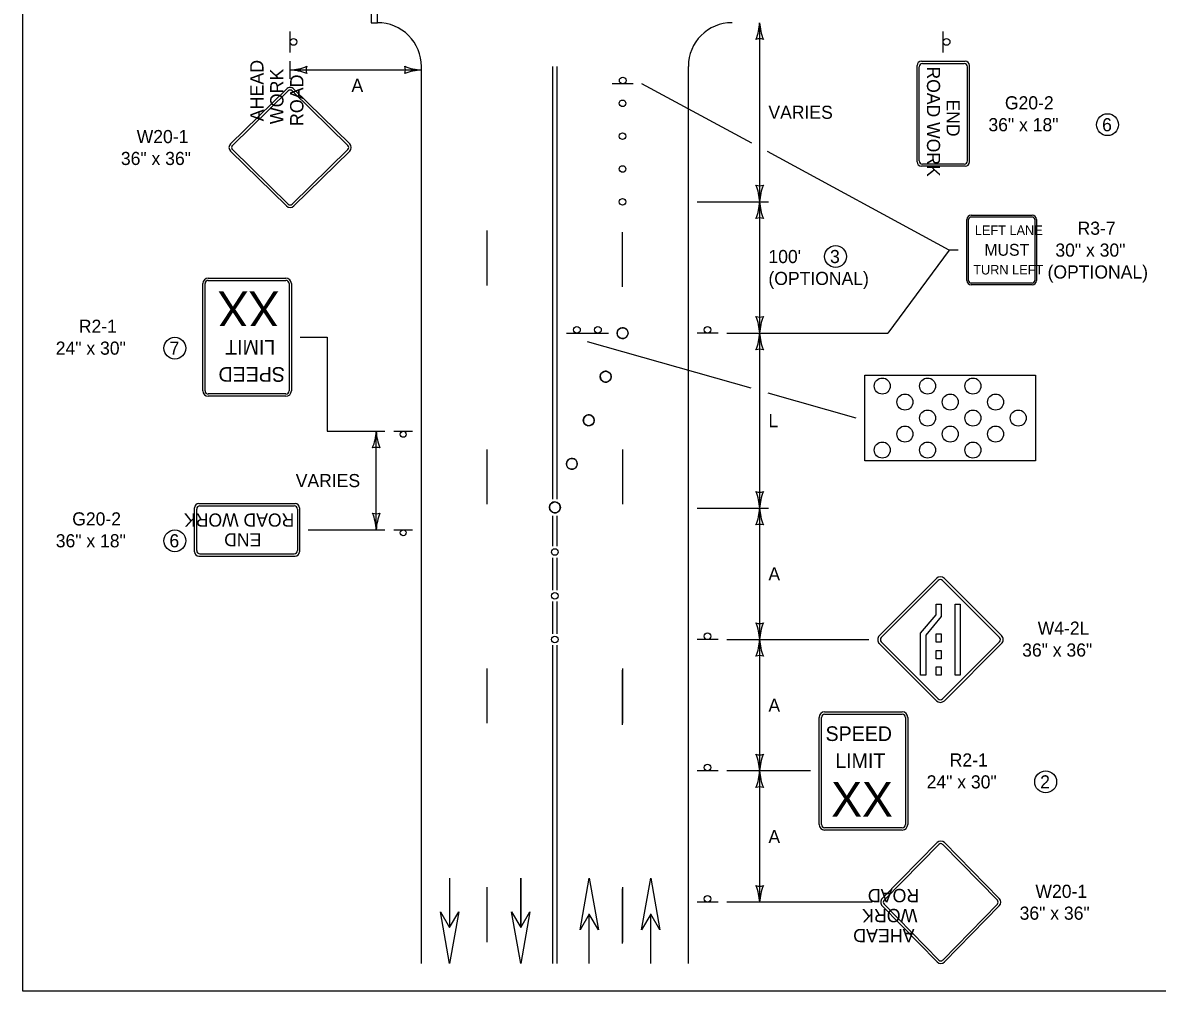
# Model space of a CAD drawing. Extents: x 49991.4 to 50021, y 49987.6 to 50011.4.
# Drawn here: x 49999.38 to 50004.57, y 49987.8 to 49992.22 of the extents above; entities that cross this region are included whole.
import ezdxf

# ---------------------------------------------------------------- set-up
doc = ezdxf.new("R2010")
doc.units = 0
for name, color, linetype in [('Level 1', 7, 'Continuous'), ('Level 2', 7, 'Continuous'), ('Level 3', 7, 'Continuous')]:
    doc.layers.add(name, color=color, linetype=linetype)

msp = doc.modelspace()

# ---------------------------------------------------------------- linework, layer by layer
at = {"layer": 'Level 1'}
for p, q in [((50000.6058, 49992.088), (50000.6058, 49992.184)), ((50003.5911, 49992.088), (50003.5911, 49992.184)), ((50001.2058, 49987.9261), (50001.2058, 49992.024)), ((50001.8058, 49990.0474), (50001.8058, 49992.024)), ((50001.8258, 49990.0474), (50001.8258, 49992.024)), ((50002.4258, 49987.9261), (50002.4258, 49992.024)), ((50003.471, 49991.5881), (50003.471, 49992.0281)), ((50003.4811, 49991.593), (50003.4811, 49992.023)), ((50003.4911, 49992.048), (50003.6911, 49992.048)), ((50003.4961, 49992.038), (50003.6861, 49992.038)), ((50003.7011, 49991.593), (50003.7011, 49992.023)), ((50003.7111, 49991.588), (50003.7111, 49992.028)), ((50000.3335, 49991.6709), (50000.5887, 49991.921)), ((50000.3417, 49991.6626), (50000.5969, 49991.9127)), ((50000.6147, 49991.9127), (50000.87, 49991.6626)), ((50000.6229, 49991.921), (50000.8782, 49991.6709)), ((50002.1738, 49991.945), (50002.0778, 49991.945)), ((50000.5969, 49991.395), (50000.3417, 49991.6451)), ((50000.87, 49991.6451), (50000.6147, 49991.395)), ((50000.5887, 49991.3866), (50000.3335, 49991.6367)), ((50000.8782, 49991.6367), (50000.6229, 49991.3866)), ((50003.6911, 49991.568), (50003.4911, 49991.568)), ((50003.6861, 49991.578), (50003.4961, 49991.578)), ((50003.7185, 49991.3443), (50003.9971, 49991.3443)), ((50003.7185, 49991.3364), (50003.9971, 49991.3364)), ((50003.6986, 49991.0458), (50003.6986, 49991.3244)), ((50003.7065, 49991.0458), (50003.7065, 49991.3244)), ((50004.0091, 49991.3244), (50004.0091, 49991.0458)), ((50004.017, 49991.3244), (50004.017, 49991.0458)), ((50001.5059, 49991.024), (50001.5059, 49991.274)), ((50002.1254, 49991.0167), (50002.1254, 49991.2667)), ((50000.2064, 49990.5424), (50000.2064, 49991.0319)), ((50000.2169, 49990.5424), (50000.2169, 49991.0319)), ((50000.2317, 49991.0572), (50000.5861, 49991.0572)), ((50000.2317, 49991.0466), (50000.5861, 49991.0466)), ((50000.6009, 49991.0319), (50000.6009, 49990.5424)), ((50000.6114, 49991.0319), (50000.6114, 49990.5424)), ((50003.6986, 49991.0458), (50003.6986, 49991.0458)), ((50003.7065, 49991.0458), (50003.7065, 49991.0458)), ((50003.9971, 49991.0338), (50003.7185, 49991.0338)), ((50003.9971, 49991.0259), (50003.7185, 49991.0259)), ((50002.1106, 49990.8258), (50002.1106, 49990.8258)), ((50001.8687, 49990.8057), (50001.9647, 49990.8057)), ((50001.9647, 49990.8057), (50002.0607, 49990.8057)), ((50002.5618, 49990.8057), (50002.4658, 49990.8057)), ((50002.0332, 49990.6268), (50002.0332, 49990.6268)), ((50000.5861, 49990.5277), (50000.2317, 49990.5277)), ((50000.5861, 49990.5171), (50000.2317, 49990.5171)), ((50000.4089, 49990.5171), (50000.4089, 49990.5171)), ((50001.9558, 49990.4277), (50001.9558, 49990.4277)), ((50001.0794, 49990.3571), (50001.1658, 49990.3571)), ((50001.5059, 49990.024), (50001.5059, 49990.274)), ((50002.1259, 49990.024), (50002.1259, 49990.274)), ((50001.8784, 49990.2287), (50001.8784, 49990.2287)), ((50000.1688, 49989.8071), (50000.1688, 49990.0071)), ((50000.1788, 49989.8121), (50000.1788, 49990.0021)), ((50000.1889, 49990.0271), (50000.6289, 49990.0271)), ((50000.1938, 49990.0171), (50000.6238, 49990.0171)), ((50000.6388, 49990.0021), (50000.6388, 49989.8121)), ((50000.6488, 49990.0071), (50000.6488, 49989.8071)), ((50001.8058, 49989.8318), (50001.8058, 49989.9715)), ((50001.8258, 49989.8318), (50001.8258, 49989.9715)), ((50001.0794, 49989.9071), (50001.1658, 49989.9071)), ((50000.1888, 49989.7871), (50000.6288, 49989.7871)), ((50000.1938, 49989.7971), (50000.6238, 49989.7971)), ((50001.8058, 49989.6318), (50001.8058, 49989.7795)), ((50001.8258, 49989.6318), (50001.8258, 49989.7795)), ((50003.2988, 49989.4242), (50003.5594, 49989.6848)), ((50003.3076, 49989.4155), (50003.5682, 49989.6761)), ((50003.588, 49989.6762), (50003.8484, 49989.4154)), ((50003.5968, 49989.6849), (50003.8572, 49989.4242)), ((50001.8058, 49989.4318), (50001.8058, 49989.5795)), ((50001.8258, 49989.4318), (50001.8258, 49989.5795)), ((50003.4874, 49989.4355), (50003.5586, 49989.5194)), ((50003.5586, 49989.5194), (50003.5586, 49989.5679)), ((50003.5586, 49989.5679), (50003.582, 49989.5679)), ((50003.582, 49989.5679), (50003.582, 49989.5108)), ((50003.645, 49989.2436), (50003.6452, 49989.5679)), ((50003.6452, 49989.5679), (50003.6687, 49989.5678)), ((50003.6687, 49989.5678), (50003.6684, 49989.2436)), ((50003.582, 49989.5108), (50003.511, 49989.4264)), ((50003.4874, 49989.2432), (50003.4874, 49989.4355)), ((50003.511, 49989.4264), (50003.5109, 49989.2432)), ((50003.5585, 49989.3937), (50003.5585, 49989.4313)), ((50003.5585, 49989.4313), (50003.5819, 49989.4313)), ((50003.5819, 49989.4313), (50003.5819, 49989.3937)), ((50001.8058, 49987.9261), (50001.8058, 49989.3795)), ((50001.8258, 49987.9261), (50001.8258, 49989.3795)), ((50002.5618, 49989.4057), (50002.4658, 49989.4057)), ((50003.5594, 49989.1262), (50003.2988, 49989.387)), ((50003.5681, 49989.135), (50003.3075, 49989.3958)), ((50003.5819, 49989.3937), (50003.5585, 49989.3937)), ((50003.8485, 49989.3959), (50003.588, 49989.1349)), ((50003.8573, 49989.3871), (50003.5967, 49989.1261)), ((50003.5584, 49989.3184), (50003.5584, 49989.356)), ((50003.5584, 49989.356), (50003.5819, 49989.356)), ((50003.5819, 49989.3184), (50003.5584, 49989.3184)), ((50003.5819, 49989.356), (50003.5819, 49989.3184)), ((50001.5059, 49989.024), (50001.5059, 49989.274)), ((50001.5059, 49989.024), (50001.5059, 49989.274)), ((50002.1254, 49989.0167), (50002.1254, 49989.2667)), ((50002.1259, 49989.024), (50002.1259, 49989.274)), ((50002.1259, 49989.024), (50002.1259, 49989.274)), ((50003.5584, 49989.2431), (50003.5584, 49989.2808)), ((50003.5584, 49989.2808), (50003.5818, 49989.2808)), ((50003.5818, 49989.2808), (50003.5818, 49989.2431)), ((50003.5109, 49989.2432), (50003.4874, 49989.2432)), ((50003.5818, 49989.2431), (50003.5584, 49989.2431)), ((50003.6684, 49989.2436), (50003.645, 49989.2436)), ((50003.0235, 49988.5609), (50003.0235, 49989.0504)), ((50003.0341, 49988.5609), (50003.0341, 49989.0504)), ((50003.0488, 49989.0757), (50003.4032, 49989.0757)), ((50003.0488, 49989.0651), (50003.4032, 49989.0651)), ((50003.226, 49989.0757), (50003.226, 49989.0757)), ((50003.418, 49989.0504), (50003.418, 49988.5609)), ((50003.4286, 49989.0504), (50003.4286, 49988.5609)), ((50002.5618, 49988.8057), (50002.4658, 49988.8057)), ((50003.4032, 49988.5462), (50003.0488, 49988.5462)), ((50003.4032, 49988.5356), (50003.0488, 49988.5356)), ((50003.3122, 49988.2228), (50003.5623, 49988.478)), ((50003.3206, 49988.2146), (50003.5707, 49988.4699)), ((50003.5882, 49988.4699), (50003.8383, 49988.2146)), ((50003.5965, 49988.478), (50003.8466, 49988.2228)), ((50001.3344, 49988.3162), (50001.3344, 49988.0903)), ((50001.3348, 49988.3162), (50001.3348, 49988.0903)), ((50001.5059, 49988.024), (50001.5059, 49988.274)), ((50001.5059, 49988.024), (50001.5059, 49988.274)), ((50001.6592, 49988.3162), (50001.6592, 49988.0903)), ((50001.6596, 49988.3162), (50001.6596, 49988.0903)), ((50002.1259, 49988.024), (50002.1259, 49988.274)), ((50002.1259, 49988.024), (50002.1259, 49988.274)), ((50002.1254, 49988.0167), (50002.1254, 49988.2667)), ((50002.5618, 49988.2057), (50002.4658, 49988.2057)), ((50003.5623, 49987.9334), (50003.3122, 49988.1886)), ((50003.5707, 49987.9415), (50003.3206, 49988.1968)), ((50003.8383, 49988.1968), (50003.5882, 49987.9415)), ((50003.8466, 49988.1886), (50003.5965, 49987.9334)), ((50001.9728, 49987.9261), (50001.9728, 49988.152)), ((50001.9732, 49987.9261), (50001.9732, 49988.152)), ((50002.2538, 49987.9261), (50002.2538, 49988.152)), ((50002.2542, 49987.9261), (50002.2542, 49988.152))]:
    msp.add_line(p, q, dxfattribs=at)
for points in [[(49999.3835, 49998.9992), (50016.7501, 49998.9992), (50016.7501, 49987.7988), (49999.3835, 49987.7988)], [(50004.0126, 49990.223), (50003.2329, 49990.223), (50003.2329, 49990.613), (50004.0126, 49990.613)], [(50004.0126, 49990.223), (50003.2329, 49990.223), (50003.2329, 49990.613), (50004.0126, 49990.613)], [(50001.9312, 49988.0797), (50001.9728, 49988.3162), (50002.0148, 49988.0797), (50001.9728, 49988.1519)], [(50002.2122, 49988.0797), (50002.2538, 49988.3162), (50002.2958, 49988.0797), (50002.2538, 49988.1519)], [(50001.3764, 49988.1626), (50001.3348, 49987.9261), (50001.2928, 49988.1626), (50001.3348, 49988.0904)], [(50001.7012, 49988.1626), (50001.6596, 49987.9261), (50001.6176, 49988.1626), (50001.6596, 49988.0904)]]:
    msp.add_lwpolyline(points, close=True, dxfattribs=at)
msp.add_lwpolyline([(50000.9758, 49992.224), (50001.0058, 49992.224), (50001.0058, 49992.5241), (50000.9758, 49992.5241), (50000.9758, 49992.224)], dxfattribs=at)
for centre, radius in [((50000.6209, 49992.136), 0.0152), ((50003.6062, 49992.136), 0.0152), ((50002.1258, 49991.9602), 0.0152), ((50002.1254, 49991.8557), 0.015), ((50002.1254, 49991.7057), 0.015), ((50002.1254, 49991.5557), 0.015), ((50002.1254, 49991.4057), 0.015), ((50001.9167, 49990.8209), 0.0152), ((50002.0127, 49990.8209), 0.0152), ((50002.1254, 49990.8057), 0.025), ((50002.5137, 49990.8208), 0.0152), ((50002.048, 49990.6066), 0.025), ((50003.3122, 49990.564), 0.0366), ((50003.3122, 49990.564), 0.0366), ((50003.5193, 49990.564), 0.0366), ((50003.5193, 49990.564), 0.0366), ((50003.7265, 49990.564), 0.0366), ((50003.7265, 49990.564), 0.0366), ((50003.4158, 49990.4909), 0.0366), ((50003.4158, 49990.4909), 0.0366), ((50003.6229, 49990.4909), 0.0366), ((50003.6229, 49990.4909), 0.0366), ((50003.83, 49990.4909), 0.0366), ((50003.83, 49990.4909), 0.0366), ((50003.5193, 49990.4178), 0.0366), ((50003.5193, 49990.4178), 0.0366), ((50003.7265, 49990.4178), 0.0366), ((50003.7265, 49990.4178), 0.0366), ((50003.9336, 49990.4178), 0.0366), ((50003.9336, 49990.4178), 0.0366), ((50001.9706, 49990.4076), 0.025), ((50001.1226, 49990.3434), 0.0137), ((50003.4158, 49990.3447), 0.0366), ((50003.4158, 49990.3447), 0.0366), ((50003.6229, 49990.3447), 0.0366), ((50003.6229, 49990.3447), 0.0366), ((50003.83, 49990.3447), 0.0366), ((50003.83, 49990.3447), 0.0366), ((50003.3122, 49990.2716), 0.0366), ((50003.3122, 49990.2716), 0.0366), ((50003.5193, 49990.2716), 0.0366), ((50003.5193, 49990.2716), 0.0366), ((50003.7265, 49990.2716), 0.0366), ((50003.7265, 49990.2716), 0.0366), ((50001.8932, 49990.2085), 0.025), ((50001.8158, 49990.0095), 0.025), ((50001.1226, 49989.8934), 0.0137), ((50001.8158, 49989.8057), 0.015), ((50001.8158, 49989.6057), 0.015), ((50001.8158, 49989.4057), 0.015), ((50002.5137, 49989.4208), 0.0152), ((50002.5137, 49988.8208), 0.0152), ((50002.5137, 49988.2208), 0.0152)]:
    msp.add_circle(centre, radius, dxfattribs=at)
for centre, radius, start, end in [((50001.0058, 49992.024), 0.2, 359.9999, 90), ((50002.6258, 49992.024), 0.2, 90, 180), ((50003.4911, 49992.0281), 0.02, 90, 180), ((50003.4961, 49992.023), 0.015, 90, 180), ((50003.6861, 49992.023), 0.015, 360, 90), ((50003.6911, 49992.028), 0.02, 360, 90), ((50003.4961, 49991.593), 0.015, 180, 270), ((50003.6861, 49991.593), 0.015, 270, 360), ((50003.4911, 49991.5881), 0.02, 180, 270), ((50003.6911, 49991.588), 0.02, 270, 360), ((50003.7185, 49991.3244), 0.0199, 90, 180), ((50003.7185, 49991.3244), 0.0119, 90, 180), ((50003.9971, 49991.3244), 0.0199, 0, 90), ((50003.9971, 49991.3244), 0.0119, 0, 90), ((50000.2317, 49991.0319), 0.0253, 90, 180), ((50000.2317, 49991.0319), 0.0148, 90, 180), ((50000.5861, 49991.0319), 0.0253, 360, 90), ((50000.5861, 49991.0319), 0.0148, 360, 90), ((50003.7185, 49991.0458), 0.0199, 180, 270), ((50003.7185, 49991.0458), 0.0119, 180, 270), ((50003.9971, 49991.0458), 0.0119, 270, 0), ((50003.9971, 49991.0458), 0.0199, 270, 0), ((50002.1254, 49990.8057), 0.025, 126.2526, 306.2526), ((50002.1254, 49990.8057), 0.025, 306.2526, 126.2526), ((50002.048, 49990.6066), 0.025, 126.2526, 306.2526), ((50002.048, 49990.6066), 0.025, 306.2526, 126.2526), ((50000.2317, 49990.5424), 0.0253, 180, 270), ((50000.2317, 49990.5424), 0.0148, 180, 270), ((50000.5861, 49990.5424), 0.0148, 270, 360), ((50000.5861, 49990.5424), 0.0253, 270, 360), ((50001.9706, 49990.4076), 0.025, 126.2526, 306.2526), ((50001.9706, 49990.4076), 0.025, 306.2526, 126.2526), ((50001.8932, 49990.2085), 0.025, 126.2526, 306.2526), ((50001.8932, 49990.2085), 0.025, 306.2526, 126.2526), ((50000.1889, 49990.0071), 0.02, 90, 180), ((50000.1938, 49990.0021), 0.015, 90, 180), ((50000.6238, 49990.0021), 0.015, 360, 90), ((50000.6289, 49990.0071), 0.02, 360, 90), ((50001.8158, 49990.0095), 0.025, 126.2526, 306.2526), ((50001.8158, 49990.0095), 0.025, 306.2526, 126.2526), ((50000.1888, 49989.8071), 0.02, 180, 270), ((50000.1938, 49989.8121), 0.015, 180, 270), ((50000.6238, 49989.8121), 0.015, 270, 360), ((50000.6288, 49989.8071), 0.02, 270, 360), ((50003.578, 49989.6662), 0.0263, 45.0001, 134.9999), ((50003.5781, 49989.6663), 0.0139, 45.0001, 134.9999), ((50003.3175, 49989.4057), 0.0263, 134.9999, 225.0001), ((50003.3175, 49989.4057), 0.0139, 134.9999, 225.0001), ((50003.8388, 49989.4057), 0.0139, 314.9999, 45.0001), ((50003.8388, 49989.4057), 0.0263, 314.9999, 45.0001), ((50003.5781, 49989.145), 0.0263, 225.0001, 314.9999), ((50003.5781, 49989.145), 0.0139, 225.0001, 314.9999), ((50003.0488, 49989.0504), 0.0253, 90, 180), ((50003.0488, 49989.0504), 0.0148, 90, 180), ((50003.4032, 49989.0504), 0.0253, 0, 90), ((50003.4032, 49989.0504), 0.0148, 0, 90), ((50003.0488, 49988.5609), 0.0253, 180, 270), ((50003.0488, 49988.5609), 0.0148, 180, 270), ((50003.4032, 49988.5609), 0.0148, 270, 360), ((50003.4032, 49988.5609), 0.0253, 270, 360)]:
    msp.add_arc(centre, radius, start, end, dxfattribs=at)
for centre, major_axis, ratio, start_param, end_param in [((50000.6058, 49991.904), (0.0243, 0), 0.98963, 0.785394, 2.356194), ((50000.6058, 49991.904), (0.0126, 0), 0.98, 0.785394, 2.356194), ((50000.3505, 49991.6538), (-0.0243, 0), 0.98963, 5.497795, 7.068583), ((50000.3505, 49991.6538), (-0.0126, 0), 0.98, 5.497795, 7.068583), ((50000.861, 49991.6538), (0.0126, 0), 0.98, 5.497787, 7.068583), ((50000.861, 49991.6538), (0.0243, 0), 0.98963, 5.497787, 7.068583), ((50000.6058, 49991.4037), (0.0243, 0), 0.98963, 3.926991, 5.497787), ((50000.6058, 49991.4037), (0.0126, 0), 0.98, 3.926991, 5.497787), ((50003.5794, 49988.4609), (0, 0.0243), 0.98963, 5.497787, 7.068583), ((50003.5794, 49988.4609), (0, 0.0126), 0.98, 5.497787, 7.068583), ((50003.3293, 49988.2057), (0, 0.0243), 0.98963, 0.785394, 2.356194), ((50003.8295, 49988.2057), (0, 0.0243), 0.98963, 3.926991, 5.497787), ((50003.3293, 49988.2057), (0, 0.0126), 0.98, 0.785394, 2.356194), ((50003.8295, 49988.2057), (0, 0.0126), 0.98, 3.926991, 5.497787), ((50003.5794, 49987.9504), (0, -0.0243), 0.98963, 5.497795, 7.068583), ((50003.5794, 49987.9504), (0, -0.0126), 0.98, 5.497795, 7.068583)]:
    msp.add_ellipse(centre, major_axis=major_axis, ratio=ratio, start_param=start_param, end_param=end_param, dxfattribs=at)
at = {"layer": 'Level 2'}
for centre in [(50004.3414, 49991.758), (50003.0986, 49991.1557), (50000.0787, 49990.7372), (50000.0787, 49989.8571), (50004.059, 49988.7556)]:
    msp.add_circle(centre, 0.0501, dxfattribs=at)
at = {"layer": 'Level 3'}
for p, q in [((50002.7518, 49991.4057), (50002.7518, 49992.224)), ((50000.6058, 49991.968), (50000.6058, 49992.048)), ((50000.6058, 49992.008), (50001.2058, 49992.008)), ((50002.7166, 49991.6731), (50002.2138, 49991.945)), ((50003.6186, 49991.1851), (50002.787, 49991.635)), ((50002.4658, 49991.4057), (50002.7918, 49991.4057)), ((50002.7518, 49990.8057), (50002.7518, 49991.4057)), ((50003.6186, 49991.1851), (50003.337, 49990.8057)), ((50003.6586, 49991.1851), (50003.6186, 49991.1851)), ((50000.6514, 49990.7872), (50000.7755, 49990.7872)), ((50000.7755, 49990.7872), (50000.7755, 49990.3571)), ((50002.7133, 49990.5538), (50001.9647, 49990.7657)), ((50002.6018, 49990.8057), (50003.337, 49990.8057)), ((50002.7518, 49990.0057), (50002.7518, 49990.8057)), ((50003.1929, 49990.418), (50002.7903, 49990.532)), ((50000.7755, 49990.3571), (50001.0394, 49990.3571)), ((50000.9994, 49989.9071), (50000.9994, 49990.3571)), ((50002.4658, 49990.0057), (50002.7918, 49990.0057)), ((50002.7518, 49989.4057), (50002.7518, 49990.0057)), ((50000.6888, 49989.9071), (50001.0394, 49989.9071)), ((50002.6018, 49989.4057), (50003.2512, 49989.4057)), ((50002.7518, 49988.8057), (50002.7518, 49989.4057)), ((50002.9835, 49988.8057), (50002.6018, 49988.8057)), ((50002.7518, 49988.2057), (50002.7518, 49988.8057)), ((50003.2653, 49988.2057), (50002.6018, 49988.2057))]:
    msp.add_line(p, q, dxfattribs=at)
for centre, radius, start, end in [((50002.5296, 49992.2331), 0.2223, 337.456, 357.6395), ((50002.9845, 49992.2355), 0.233, 182.8273, 202.0772), ((50002.7518, 49992.0958), 0.0548, 72.1388, 107.8612), ((50000.5943, 49992.2407), 0.233, 272.8273, 292.0772), ((50000.5966, 49991.7859), 0.2223, 67.456, 87.6395), ((50000.734, 49992.008), 0.0548, 162.1388, 197.8612), ((50001.2149, 49992.2301), 0.2223, 247.456, 267.6395), ((50001.0776, 49992.008), 0.0548, 342.1388, 17.8612), ((50001.2173, 49991.7753), 0.233, 92.8273, 112.0772), ((50002.7518, 49991.5339), 0.0548, 252.1388, 287.8612), ((50002.5191, 49991.3942), 0.233, 2.8273, 22.0772), ((50002.9739, 49991.3965), 0.2223, 157.456, 177.6395), ((50002.5296, 49991.4148), 0.2223, 337.456, 357.6395), ((50002.9845, 49991.4171), 0.233, 182.8273, 202.0772), ((50002.7518, 49991.2774), 0.0548, 72.1388, 107.8612), ((50002.7518, 49990.9339), 0.0548, 252.1388, 287.8612), ((50002.5191, 49990.7942), 0.233, 2.8273, 22.0772), ((50002.9739, 49990.7965), 0.2223, 157.456, 177.6395), ((50002.5296, 49990.8148), 0.2223, 337.456, 357.6395), ((50002.9845, 49990.8171), 0.233, 182.8273, 202.0772), ((50002.7518, 49990.6774), 0.0548, 72.1388, 107.8612), ((50000.7772, 49990.3662), 0.2223, 337.456, 357.6395), ((50001.2321, 49990.3686), 0.233, 182.8273, 202.0772), ((50000.9994, 49990.2289), 0.0548, 72.1388, 107.8612), ((50002.7518, 49990.1339), 0.0548, 252.1388, 287.8612), ((50002.5191, 49989.9942), 0.233, 2.8273, 22.0772), ((50002.9739, 49989.9965), 0.2223, 157.456, 177.6395), ((50002.5296, 49990.0148), 0.2223, 337.456, 357.6395), ((50002.9845, 49990.0171), 0.233, 182.8273, 202.0772), ((50000.9994, 49990.0353), 0.0548, 252.1388, 287.8612), ((50000.7667, 49989.8956), 0.233, 2.8273, 22.0772), ((50001.2215, 49989.8979), 0.2223, 157.456, 177.6395), ((50002.7518, 49989.8774), 0.0548, 72.1388, 107.8612), ((50002.7518, 49989.5339), 0.0548, 252.1388, 287.8612), ((50002.5191, 49989.3942), 0.233, 2.8273, 22.0772), ((50002.9739, 49989.3965), 0.2223, 157.456, 177.6395), ((50002.5296, 49989.4148), 0.2223, 337.456, 357.6395), ((50002.9845, 49989.4171), 0.233, 182.8273, 202.0772), ((50002.7518, 49989.2774), 0.0548, 72.1388, 107.8612), ((50002.7518, 49988.9339), 0.0548, 252.1388, 287.8612), ((50002.5191, 49988.7942), 0.233, 2.8273, 22.0772), ((50002.9739, 49988.7965), 0.2223, 157.456, 177.6395), ((50002.5296, 49988.8148), 0.2223, 337.456, 357.6395), ((50002.9845, 49988.8171), 0.233, 182.8273, 202.0772), ((50002.7518, 49988.6774), 0.0548, 72.1388, 107.8612), ((50002.7518, 49988.3339), 0.0548, 252.1388, 287.8612), ((50002.5191, 49988.1942), 0.233, 2.8273, 22.0772), ((50002.9739, 49988.1965), 0.2223, 157.456, 177.6395)]:
    msp.add_arc(centre, radius, start, end, dxfattribs=at)

# ---------------------------------------------------------------- texts
at = {"layer": 'Level 1'}
for s, height, rotation, p in [('AHEAD', 0.06086, 90, (50000.4841, 49991.7736)), ('WORK', 0.06086, 90, (50000.5754, 49991.7606)), ('ROAD WORK', 0.06, 270, (50003.5164, 49992.0239)), ('ROAD', 0.06086, 90, (50000.6666, 49991.7521)), ('END', 0.06, 270, (50003.6064, 49991.8732)), ('XX', 0.15772, 180, (50000.556, 49990.9961)), ('LIMIT', 0.06695, 180, (50000.5377, 49990.7741)), ('SPEED', 0.06695, 180, (50000.582, 49990.6504)), ('ROAD WORK', 0.06, 180, (50000.6247, 49989.9817)), ('END', 0.06, 180, (50000.474, 49989.8917)), ('ROAD', 0.06086, 180, (50003.4812, 49988.2665)), ('WORK', 0.06086, 180, (50003.4727, 49988.1753)), ('AHEAD', 0.06086, 180, (50003.4597, 49988.084))]:
    msp.add_text(s, height=height, rotation=rotation, dxfattribs=at).set_placement(p)
for s, height, p in [('LEFT LANE', 0.04352, (50003.7351, 49991.2541)), ('MUST', 0.05413, (50003.7788, 49991.1593)), ('TURN LEFT', 0.04352, (50003.7278, 49991.0737)), ('SPEED', 0.06695, (50003.0529, 49988.9424)), ('LIMIT', 0.06695, (50003.0973, 49988.8187)), ('XX', 0.15772, (50003.0789, 49988.5967))]:
    msp.add_text(s, height=height, dxfattribs=at).set_placement(p)
at = {"layer": 'Level 2'}
for s, p in [('A', (50000.8862, 49991.908)), ('W20-1', (49999.9045, 49991.6738)), ('36" x 36"', (49999.8323, 49991.5738)), ('VARIES', (50000.6314, 49990.1021)), ('A', (50002.7918, 49989.6757)), ('A', (50002.7918, 49989.0757)), ('A', (50002.7918, 49988.4757))]:
    msp.add_text(s, height=0.06, rotation=360, dxfattribs=at).set_placement(p)
for s, p in [('G20-2', (50003.8726, 49991.828)), ('VARIES', (50002.7918, 49991.7848)), ('36" x 18"', (50003.7973, 49991.728)), ('6', (50004.3169, 49991.728)), ('R3-7', (50004.2048, 49991.2551)), ("100' ", (50002.7918, 49991.1257)), ('3', (50003.0734, 49991.1257)), ('30" x 30"', (50004.1033, 49991.1551)), ('(OPTIONAL)', (50002.7918, 49991.0257)), ('(OPTIONAL)', (50004.0676, 49991.0551)), ('R2-1', (49999.6402, 49990.8072)), ('24" x 30"', (49999.5346, 49990.7072)), ('7', (50000.0549, 49990.7072)), ('L', (50002.7918, 49990.3757)), ('G20-2', (49999.6099, 49989.9271)), ('36" x 18"', (49999.5347, 49989.8271)), ('6', (50000.0542, 49989.8271)), ('W4-2L', (50004.0225, 49989.428)), ('36" x 36"', (50003.9516, 49989.328)), ('R2-1', (50003.6204, 49988.8256)), ('24" x 30"', (50003.5149, 49988.7256)), ('2', (50004.0338, 49988.7256)), ('W20-1', (50004.0122, 49988.2258)), ('36" x 36"', (50003.9399, 49988.1258))]:
    msp.add_text(s, height=0.06, dxfattribs=at).set_placement(p)

doc.saveas('drawing.dxf')
